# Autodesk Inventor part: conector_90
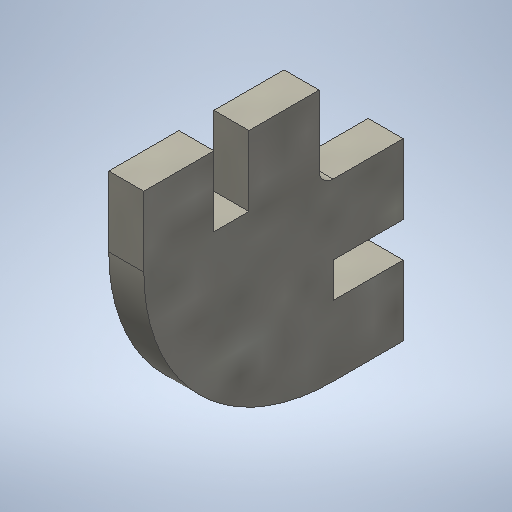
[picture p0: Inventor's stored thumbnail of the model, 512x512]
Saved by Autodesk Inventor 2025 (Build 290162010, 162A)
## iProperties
Created: 2025-02
Part Number: conector_90
Material: Paper
Document SubType Name: Modeling
Designer: BennF
Density: 0.93 g/cm^3
Appearance: Cardboard - Chipboard
Author: BennF
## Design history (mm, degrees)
sketch "Sketch2"
  geometry: L1 (-13.5, 0)-(-13.5, 5); L2 (-13.5, 5)-(-8.5, 5); L3 (-8.5, 5)-(-8.5, 0); L4 (-8.5, 0)-(-6, 0); L5 (-6, 0)-(-6, 5); L6 (-6, 5)-(-1, 5); L7 (-1, 5)-(-1, 0); L8 (0, -1)-(5, -1); L9 (5, -1)-(5, -6); L10 (5, -6)-(0, -6); L11 (0, -6)-(0, -8.5); L12 (0, -8.5)-(5, -8.5); L13 (5, -8.5)-(5, -13.5); L14 (5, -13.5)-(0, -13.5); L15 (-6, 0)-(0, -6); A1 r 1 centre (0, 0) between (-1, 0) and (0, -1); A2 r 13.5 centre (0, 0) between (-13.5, 0) and (0, -13.5); 2 further points
  constraints: 30 end point, 10 perpendicular, 5 equal length, 5 point on circle, 4 point on line, 4 tangent, 3 coincident, 2 centre point, 1 horizontal, 1 vertical
  dimensions: "d0" = 2.5 distance of L3.end L4.end (= thickness); "d1" = 5 distance of L2.end L3.end (= slot_depth); "d2" = 5 distance of L1.end L2.end (= slot_dis_1); "d3" = 1 radius of A1; "d7" = 6 distance from line of L10.end L4 (computed from slot_depth)
extrude "Extrusion1" new body sketch "Sketch2" distance "d5" = 2.5 (= thickness); taper "d6" = 0 deg
sketch "laser"
  geometry: L1 (13.5, 0)-(13.5, 5) reference; L2 (13.5, 5)-(8.5, 5) reference; L3 (8.5, 5)-(8.5, 0) reference; L4 (8.5, 0)-(6, 0) reference; L5 (6, 0)-(6, 5) reference; L6 (6, 5)-(1, 5) reference; L7 (1, 5)-(1, 0) reference; L8 (0, -1)-(-5, -1) reference; L9 (-5, -1)-(-5, -6) reference; L10 (-5, -6)-(0, -6) reference; L11 (0, -6)-(0, -8.5) reference; L12 (0, -8.5)-(-5, -8.5) reference; L13 (-5, -8.5)-(-5, -13.5) reference; L14 (-5, -13.5)-(0, -13.5) reference; A1 r 1 centre (0, 0) between (0, -1) and (1, 0) reference; A2 r 13.5 centre (0, 0) between (0, -13.5) and (13.5, 0) reference; 1 further point
  node "Projected Loop1"
body "Solid1"
other parameters: "thickness" = 2.5 [user parameter; used in 2 equation terms], "clearence" = -0.5 [user parameter], "slot_depth" = 5 [user parameter; used in 2 equation terms], "slot_dis_1" = 5 [user parameter; used in 1 equation term], "slot_dis_2" = 12 [user parameter], "slot_clearenece" = 3 [user parameter], "con_angle_1" = 20.34444 [user parameter], "con_angle_2" = 60 deg [user parameter], "con_angle_3" = 12.30959 [user parameter], "con_angle_4" = 19.10633 [user parameter], "con_angle_5" = 24.11865 [user parameter]
